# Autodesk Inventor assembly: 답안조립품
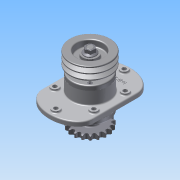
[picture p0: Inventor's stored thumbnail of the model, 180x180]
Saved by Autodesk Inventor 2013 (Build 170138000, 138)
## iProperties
Created: 2015-02
Part Number: 답안조립품
Document SubType Name: Assembly
Designer: Administrator
Author: Administrator
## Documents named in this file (12)
- C:\Documents and Settings\Administrator\바탕 화면\450208V1011\답안조립품.iam
- C:\Documents and Settings\Administrator\바탕 화면\450208V1011\1-본체.ipt
- C:\Documents and Settings\Administrator\바탕 화면\450208V1011\2-커버.ipt
- C:\Documents and Settings\Administrator\바탕 화면\450208V1011\6-베어링 6206.ipt
- C:\Documents and Settings\Administrator\바탕 화면\450208V1011\3-축.ipt
- C:\Documents and Settings\Administrator\바탕 화면\450208V1011\7-부시.ipt
- C:\Documents and Settings\Administrator\바탕 화면\450208V1011\8-오일실 30x42.ipt
- C:\Documents and Settings\Administrator\바탕 화면\450208V1011\10-M6.ipt
- C:\Documents and Settings\Administrator\바탕 화면\450208V1011\11-키 6x6.ipt
- C:\Documents and Settings\Administrator\바탕 화면\450208V1011\4-V벨트풀리.ipt
- C:\Documents and Settings\Administrator\바탕 화면\450208V1011\5-체인 스프로킷.ipt
- C:\Documents and Settings\Administrator\바탕 화면\450208V1011\9-M16-너트.ipt
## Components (23 placed, 11 different names)
1. 1-본체:1
2. 2-커버:1
3. 2-커버:2
4. 6-베어링 6206:1
5. 3-축:1 — 각도:1, 각도:2, 각도:6, 각도:7
6. 7-부시:1
7. 6-베어링 6206:2
8. 8-8-오일실 30x42:1
9. 8-8-오일실 30x42:2
10. 11-키 6x6:1 — 각도:1, 각도:3
11. 11-키 6x6:2 — 각도:2, 각도:4
12. 4-V벨트풀리:1 — 각도:3
13. 5-체인 스프로킷:1 — 각도:4
14. 9-M16 너트:1 — 각도:6
15. 9-M16 너트:2 — 각도:7
16. 10-M6:2
17. 10-M6:3
18. 10-M6:4
19. 10-M6:5
20. 10-M6:1
21. 10-M6:6
22. 10-M6:7
23. 10-M6:8
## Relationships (6: Angle 6)
- 각도:1 [Angle]: 3-축:1 ↔ 11-키 6x6:1
- 각도:2 [Angle]: 3-축:1 ↔ 11-키 6x6:2
- 각도:3 [Angle]: 11-키 6x6:1 ↔ 4-V벨트풀리:1
- 각도:4 [Angle]: 11-키 6x6:2 ↔ 5-체인 스프로킷:1
- 각도:6 [Angle]: 3-축:1 ↔ 9-M16 너트:1
- 각도:7 [Angle]: 3-축:1 ↔ 9-M16 너트:2
